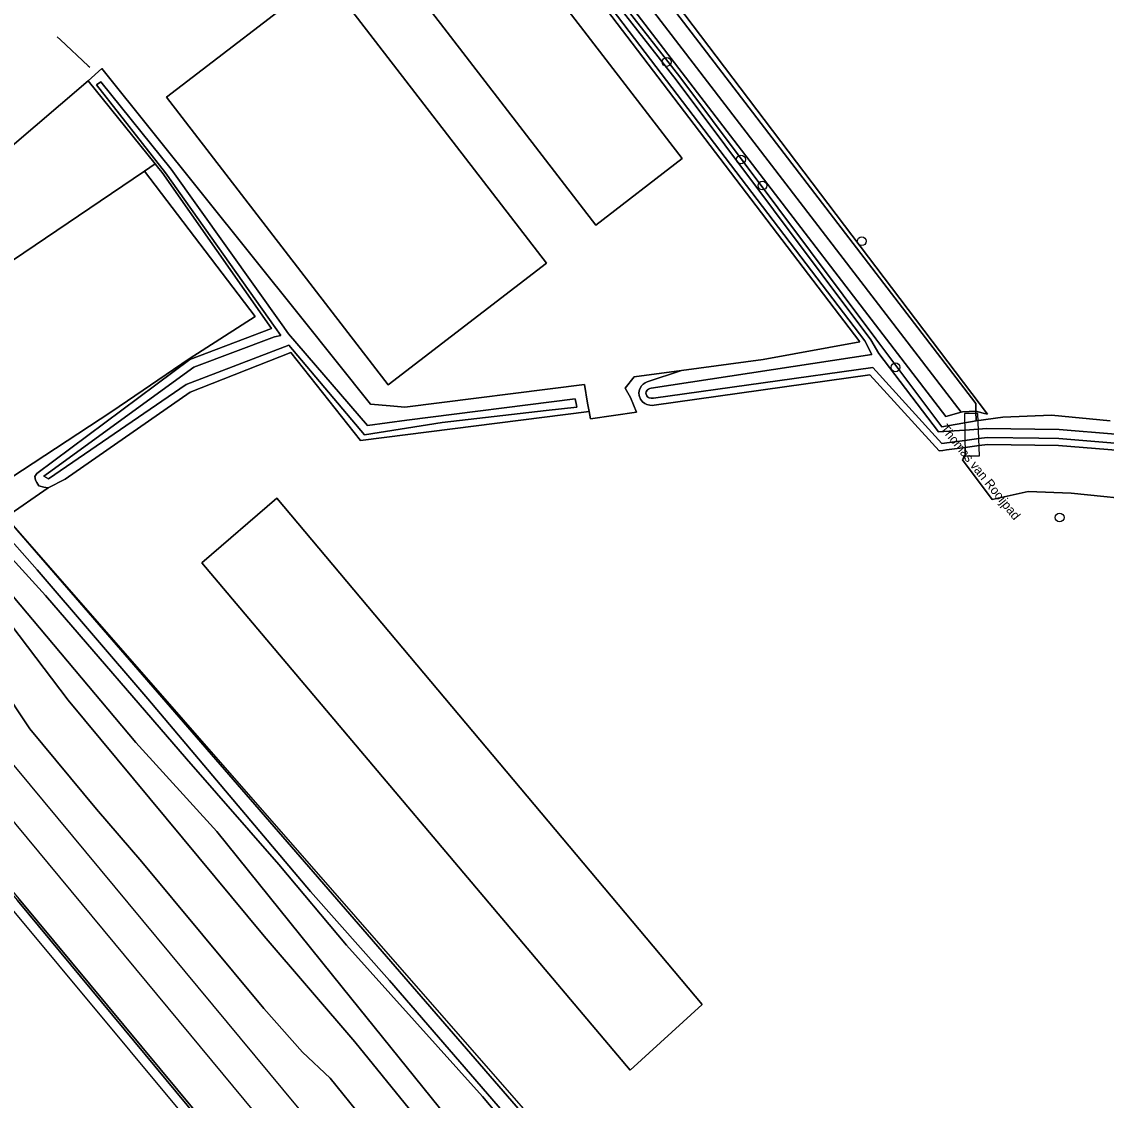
# Model space of a CAD drawing. Extents: x 164494 to 166241, y 382475 to 384495.
# Drawn here: x 165029.6 to 165148.9, y 382781.9 to 382900.5 of the extents above; entities that cross this region are included whole.
import ezdxf

# ---------------------------------------------------------------- set-up
doc = ezdxf.new("R2010")
doc.units = 0
for name, color, linetype in [('IMGEO_Boom', 7, 'Continuous'), ('IMGEO_Dek', 7, 'Continuous'), ('IMGEO_Duiker', 7, 'Continuous'), ('IMGEO_Erf', 7, 'Continuous'), ('IMGEO_Geluidsscherm', 7, 'Continuous'), ('IMGEO_Grasland_agrarisch', 7, 'Continuous'), ('IMGEO_Grasland_overig', 7, 'Continuous'), ('IMGEO_Groenvoorziening', 7, 'Continuous'), ('IMGEO_Hek', 7, 'Continuous'), ('IMGEO_Loofbos', 7, 'Continuous'), ('IMGEO_Muur', 7, 'Continuous'), ('IMGEO_Oever', 7, 'Continuous'), ('IMGEO_Open_loods', 7, 'Continuous'), ('IMGEO_Openbare_ruimte_label', 7, 'Continuous'), ('IMGEO_Pand', 7, 'Continuous'), ('IMGEO_Spoor', 7, 'Continuous'), ('IMGEO_Spoorbaan_halfverhard', 7, 'Continuous'), ('IMGEO_Terreindeel_zand', 7, 'Continuous'), ('IMGEO_Voetpad_open', 7, 'Continuous'), ('IMGEO_Waterloop', 7, 'Continuous')]:
    doc.layers.add(name, color=color, linetype=linetype)

msp = doc.modelspace()

# ---------------------------------------------------------------- linework, layer by layer
at = {"layer": 'IMGEO_Boom'}
for centre in [(165100.52, 382896.08), (165108.68, 382885.35), (165111.05, 382882.49), (165121.97, 382876.37), (165125.68, 382862.5), (165143.72, 382846)]:
    msp.add_circle(centre, 0.489, dxfattribs=at)
at = {"layer": 'IMGEO_Dek'}
msp.add_lwpolyline([(165134.72, 382857.43), (165133.26, 382857.44), (165133.35, 382852.77), (165134.9, 382852.79)], close=True, dxfattribs=at)
at = {"layer": 'IMGEO_Duiker'}
msp.add_lwpolyline([(165033.51, 382898.85), (165033.87, 382898.51), (165036.92, 382895.65), (165037.08, 382895.5)], dxfattribs=at)
at = {"layer": 'IMGEO_Erf'}
for points in [[(165066.6, 382948.67), (165135.81, 382857.34), (165135.31, 382857.48), (165134.52, 382857.7), (165134.55, 382856.63), (165137.47, 382857.02), (165142.85, 382857.23), (165149.29, 382856.63)], [(165007.04, 382918.4), (165019.13, 382899.87), (165028.02, 382886.4), (165036.89, 382893.98), (165038.4, 382895.36), (165060.39, 382867.92), (165067.96, 382858.46), (165070.13, 382858.26), (165071.71, 382858.12), (165091.47, 382860.62), (165091.82, 382858.55), (165091.98, 382857.66), (165092.13, 382856.83), (165097.2, 382857.59), (165096.55, 382859.18), (165095.94, 382860.23), (165096.95, 382861.46), (165102.13, 382862.15), (165111.11, 382863.35), (165121.76, 382865.31), (165087.09, 382910.83)]]:
    msp.add_lwpolyline(points, dxfattribs=at)
for points in [[(165068.39, 382909.77), (165077.89, 382917.07), (165102.23, 382885.46), (165092.72, 382878.14)], [(165062.93, 382905.58), (165087.31, 382873.97), (165069.89, 382860.57), (165045.51, 382892.2)]]:
    msp.add_lwpolyline(points, close=True, dxfattribs=at)
at = {"layer": 'IMGEO_Geluidsscherm'}
for points in [[(164967.63, 382879.18), (164968.42, 382878.23), (164969.05, 382877.2), (164972.8, 382871.38), (164985.66, 382855.99), (164987.91, 382853.25), (164988.14, 382852.97), (164988.99, 382851.92), (164989.37, 382851.47), (164991.3, 382849.12), (164999.17, 382839.73), (165029.12, 382803.9), (165050.12, 382778.61)], [(164967.82, 382879.34), (164968.62, 382878.38), (164969.26, 382877.33), (164973.01, 382871.52), (164985.85, 382856.15), (164988.33, 382853.13), (164989.19, 382852.08), (164991.49, 382849.28), (164999.36, 382839.9), (165029.31, 382804.06), (165050.54, 382778.5), (165051.4, 382777.46), (165054.48, 382773.76), (165066.57, 382759.13), (165083.41, 382739), (165089.76, 382731.36), (165108.9, 382708.37), (165112.45, 382704.1), (165112.77, 382703.72), (165113.64, 382702.68), (165126.37, 382687.38), (165133.17, 382679.13), (165141.63, 382668.9), (165151.85, 382656.58)]]:
    msp.add_lwpolyline(points, dxfattribs=at)
at = {"layer": 'IMGEO_Grasland_agrarisch'}
for points in [[(165007.04, 382918.4), (165006.82, 382918.81), (164995.87, 382903.23), (164991.28, 382896.51), (164988.37, 382892.57), (164988.58, 382892.31), (165012.89, 382863.66), (165043.1, 382884.07), (165044.28, 382884.87), (165036.89, 382893.98), (165028.02, 382886.4), (165019.13, 382899.87)], [(165057.65, 382848.13), (165104.41, 382792.47), (165096.49, 382785.26), (165049.42, 382841.01)]]:
    msp.add_lwpolyline(points, close=True, dxfattribs=at)
for points in [[(165153.59, 382847.8), (165144.99, 382848.66), (165140.26, 382848.85), (165136.29, 382847.99), (165133.03, 382852.34), (165133.35, 382852.77), (165133.33, 382853.7), (165131.27, 382853.43), (165130.88, 382853.38), (165130.48, 382853.33), (165122.87, 382861.67), (165099.15, 382858.33), (165098.93, 382858.32), (165098.68, 382858.33), (165098.32, 382858.42), (165098.11, 382858.53), (165097.87, 382858.72), (165097.64, 382859), (165097.53, 382859.29), (165097.49, 382859.4), (165097.46, 382859.71), (165097.52, 382860.07), (165097.74, 382860.47), (165097.93, 382860.66), (165098.17, 382860.81), (165098.39, 382860.91), (165102.13, 382862.15), (165096.95, 382861.46), (165095.94, 382860.23), (165096.55, 382859.18), (165097.2, 382857.59), (165092.13, 382856.83), (165091.98, 382857.66), (165066.86, 382854.46), (165059.2, 382864.13), (165048.13, 382859.76), (165034.39, 382850.21), (165032.5, 382849.27), (165027.86, 382846.04)], [(165028.15, 382845.7), (165139.3, 382717.42)]]:
    msp.add_lwpolyline(points, dxfattribs=at)
at = {"layer": 'IMGEO_Grasland_overig'}
for points in [[(165134.51, 382858.52), (165038.2, 382984.19), (165036.98, 382982.49), (165132.89, 382857.57), (165133.05, 382857.62), (165134.52, 382857.7)], [(165026.88, 382847.17), (165027.86, 382846.04), (165032.5, 382849.27), (165032.04, 382849.32), (165031.48, 382849.48), (165031.25, 382849.85), (165031.1, 382850.09), (165031.04, 382850.51), (165031.27, 382850.82), (165048.07, 382863.36), (165057.06, 382866.76), (165045.06, 382883.91), (165044.69, 382884.36), (165044.28, 382884.87), (165043.1, 382884.07), (165055.26, 382868.09), (165048.01, 382863.43), (165039.52, 382857.65), (165028.42, 382850.36), (165025.74, 382848.52)]]:
    msp.add_lwpolyline(points, close=True, dxfattribs=at)
for points in [[(165155.82, 382852.91), (165143.59, 382853.92), (165135.79, 382854.03), (165134.86, 382853.91), (165133.33, 382853.7), (165133.35, 382852.77), (165133.03, 382852.34), (165136.29, 382847.99), (165140.26, 382848.85), (165144.99, 382848.66), (165153.59, 382847.8)], [(165087.94, 382765.77), (165064.84, 382794.37), (165051.05, 382811.5), (165042.16, 382821.28), (165026.33, 382840.06)], [(165026.66, 382836.49), (165034.71, 382825.91), (165056.25, 382799.97), (165066.23, 382788.35), (165075.72, 382776.67)], [(165075.72, 382776.67), (165066.23, 382788.35), (165056.25, 382799.97), (165034.71, 382825.91), (165026.66, 382836.49)], [(165027.24, 382827.67), (165030.51, 382822.78), (165037.83, 382813.94), (165042.8, 382808.15), (165056.22, 382792.04), (165060.47, 382787.24), (165063.5, 382784.35), (165067.07, 382779.96)]]:
    msp.add_lwpolyline(points, dxfattribs=at)
at = {"layer": 'IMGEO_Groenvoorziening'}
for points in [[(165038.2, 382984.19), (165134.51, 382858.52), (165134.52, 382857.7), (165135.31, 382857.48), (165135.81, 382857.34), (165066.6, 382948.67), (165038.85, 382985.1)], [(165131.23, 382857.09), (165132.89, 382857.57), (165036.98, 382982.49), (165035.85, 382980.91), (165034.93, 382979.62), (165037.01, 382978.24), (165054.29, 382956.45), (165062.25, 382947.03)], [(165062.25, 382947.03), (165054.29, 382956.45), (165055.08, 382954.35), (165101.95, 382894.43), (165123.53, 382865.63), (165130.79, 382855.95), (165133.08, 382856.38), (165134.55, 382856.63), (165134.52, 382857.7), (165133.05, 382857.62), (165132.89, 382857.57), (165131.23, 382857.09)]]:
    msp.add_lwpolyline(points, close=True, dxfattribs=at)
for points in [[(165025.58, 382806.41), (165049.53, 382777.72)], [(165050.12, 382778.61), (165029.12, 382803.9)]]:
    msp.add_lwpolyline(points, dxfattribs=at)
at = {"layer": 'IMGEO_Hek'}
for points in [[(165038.85, 382985.1), (165066.6, 382948.67), (165135.81, 382857.34), (165135.31, 382857.48)], [(165132.89, 382857.57), (165131.23, 382857.09), (165062.25, 382947.03)], [(164973.54, 382889.66), (164975.81, 382891.38), (164981.3, 382895.69), (164983.94, 382897.77), (164985.02, 382896.52), (164988.37, 382892.57), (164988.58, 382892.31), (165012.89, 382863.66), (165025.74, 382848.52), (165028.15, 382845.7), (165085.5, 382780.16), (165088.54, 382776.69), (165137.4, 382721.35), (165139.82, 382718.71), (165140.36, 382718.08), (165158.11, 382697.26)], [(165133.05, 382857.62), (165132.89, 382857.57)], [(165135.31, 382857.48), (165134.52, 382857.7)], [(165096.49, 382785.26), (165049.42, 382841.01), (165057.65, 382848.13), (165104.41, 382792.47), (165096.49, 382785.26)]]:
    msp.add_lwpolyline(points, dxfattribs=at)
at = {"layer": 'IMGEO_Loofbos'}
msp.add_lwpolyline([(165104.41, 382792.47), (165057.65, 382848.13), (165049.42, 382841.01), (165096.49, 382785.26)], close=True, dxfattribs=at)
at = {"layer": 'IMGEO_Muur'}
for points in [[(165029.12, 382803.9), (165050.12, 382778.61)], [(165050.54, 382778.5), (165029.31, 382804.06)]]:
    msp.add_lwpolyline(points, dxfattribs=at)
at = {"layer": 'IMGEO_Oever'}
for points in [[(165054.63, 382954.09), (165101.55, 382894.12), (165122.97, 382865.53), (165123.85, 382864.03), (165130.41, 382855.41), (165133.29, 382855.61), (165134.79, 382855.72), (165135.68, 382855.78), (165143.67, 382855.67), (165156.07, 382854.65)], [(165149.29, 382856.63), (165142.85, 382857.23), (165137.47, 382857.02), (165134.55, 382856.63), (165133.08, 382856.38), (165130.79, 382855.95), (165123.53, 382865.63), (165101.95, 382894.43), (165055.08, 382954.35)], [(165155.93, 382853.67), (165143.62, 382854.69), (165141.45, 382854.72), (165135.74, 382854.8), (165134.83, 382854.68), (165133.31, 382854.48), (165130.78, 382854.15), (165127.15, 382858.12), (165123.17, 382862.49), (165099.08, 382859.1), (165098.94, 382859.1), (165098.8, 382859.1), (165098.6, 382859.15), (165098.53, 382859.19), (165098.41, 382859.28), (165098.32, 382859.38), (165098.25, 382859.57), (165098.24, 382859.67), (165098.27, 382859.81), (165098.37, 382860), (165098.42, 382860.05), (165098.53, 382860.12), (165098.67, 382860.18), (165098.81, 382860.23), (165123.08, 382863.91), (165122.32, 382865.41), (165087.5, 382911.14)], [(165087.09, 382910.83), (165121.76, 382865.31), (165111.11, 382863.35), (165102.13, 382862.15), (165098.39, 382860.91), (165098.17, 382860.81), (165097.93, 382860.66), (165097.74, 382860.47), (165097.52, 382860.07), (165097.46, 382859.71), (165097.49, 382859.4), (165097.53, 382859.29), (165097.64, 382859), (165097.87, 382858.72), (165098.11, 382858.53), (165098.32, 382858.42), (165098.68, 382858.33), (165098.93, 382858.32), (165099.15, 382858.33), (165122.87, 382861.67), (165130.48, 382853.33), (165130.88, 382853.38), (165131.27, 382853.43), (165133.33, 382853.7), (165134.86, 382853.91), (165135.79, 382854.03), (165143.59, 382853.92), (165155.82, 382852.91)]]:
    msp.add_lwpolyline(points, dxfattribs=at)
for points in [[(165091.98, 382857.66), (165091.82, 382858.55), (165091.47, 382860.62), (165071.71, 382858.12), (165070.13, 382858.26), (165067.96, 382858.46), (165060.39, 382867.92), (165038.4, 382895.36), (165036.89, 382893.98), (165044.28, 382884.87), (165044.69, 382884.36), (165045.06, 382883.91), (165057.06, 382866.76), (165048.07, 382863.36), (165031.27, 382850.82), (165031.04, 382850.51), (165031.1, 382850.09), (165031.25, 382849.85), (165031.48, 382849.48), (165032.04, 382849.32), (165032.5, 382849.27), (165034.39, 382850.21), (165048.13, 382859.76), (165059.2, 382864.13), (165066.86, 382854.46)], [(165038.29, 382893.89), (165046.03, 382884.28), (165058.24, 382867.17), (165058.94, 382866.19), (165067.62, 382856.11), (165071.96, 382856.69), (165090.45, 382859.05), (165090.61, 382858.34), (165090.65, 382858.14), (165087.27, 382857.75), (165075.85, 382856.45), (165067.28, 382855.1), (165058.97, 382864.96), (165047.68, 382860.61), (165032.53, 382850.25), (165032.02, 382850.56), (165032.53, 382850.91), (165048.53, 382862.52), (165057.39, 382865.86), (165058.11, 382866.02), (165057.48, 382866.9), (165045.41, 382883.88), (165037.84, 382893.56)], [(165028.15, 382845.7), (165027.12, 382844.95), (165031.29, 382840.23), (165043.46, 382826.05), (165061.34, 382804.88), (165070.04, 382795.12), (165083.17, 382779.94), (165086.92, 382776.02), (165096.77, 382765.03), (165105.02, 382754.95), (165119.18, 382738.24), (165138.17, 382716.84), (165138.56, 382717.02), (165173.63, 382676.45), (165158.11, 382697.26), (165139.3, 382717.42)], [(165026.07, 382844.19), (165024.02, 382842.71), (165026.33, 382840.06), (165042.16, 382821.28), (165051.05, 382811.5), (165064.84, 382794.37), (165087.94, 382765.77), (165094.27, 382759.82), (165097.07, 382758.22), (165099.41, 382756.22), (165102.09, 382753.62), (165109.2, 382746.55), (165114.26, 382740.8), (165135.14, 382715.41), (165137.45, 382716.5), (165119.24, 382737.14), (165101.16, 382758.17), (165087.4, 382773.84), (165080.27, 382782.34), (165065.31, 382798.98), (165057.87, 382807.85), (165047.71, 382819.46), (165032.21, 382837.42), (165027.04, 382843.06)]]:
    msp.add_lwpolyline(points, close=True, dxfattribs=at)
at = {"layer": 'IMGEO_Open_loods'}
msp.add_lwpolyline([(165077.89, 382917.07), (165068.39, 382909.77), (165092.72, 382878.14), (165102.23, 382885.46)], close=True, dxfattribs=at)
at = {"layer": 'IMGEO_Pand'}
msp.add_lwpolyline([(165062.93, 382905.58), (165045.51, 382892.2), (165069.89, 382860.57), (165087.31, 382873.97)], close=True, dxfattribs=at)
at = {"layer": 'IMGEO_Spoor'}
for points in [[(164971.84, 382886.62), (165028.93, 382818.52), (165059.9, 382781.2), (165071.68, 382767.17), (165111.26, 382719.76), (165163.2, 382658.4), (165174.6, 382645.25), (165185.3, 382632.69), (165237.74, 382570.35), (165244.67, 382561.92)], [(164968.87, 382884.12), (165014.68, 382829.39), (165077.86, 382753.28), (165088.51, 382740.65), (165118.9, 382704.2), (165145.22, 382672.37), (165159.72, 382654.6), (165190.85, 382616.84), (165202.75, 382602.69), (165235.6, 382563.21)]]:
    msp.add_lwpolyline(points, dxfattribs=at)
at = {"layer": 'IMGEO_Spoorbaan_halfverhard'}
for points in [[(165067.07, 382779.96), (165063.5, 382784.35), (165060.47, 382787.24), (165056.22, 382792.04), (165042.8, 382808.15), (165037.83, 382813.94), (165030.51, 382822.78), (165027.24, 382827.67)], [(165029.31, 382804.06), (165050.54, 382778.5)]]:
    msp.add_lwpolyline(points, dxfattribs=at)
at = {"layer": 'IMGEO_Terreindeel_zand'}
msp.add_lwpolyline([(165013.09, 382863.43), (165025.74, 382848.52), (165028.42, 382850.36), (165039.52, 382857.65), (165048.01, 382863.43), (165055.26, 382868.09), (165043.1, 382884.07), (165012.89, 382863.66)], close=True, dxfattribs=at)
at = {"layer": 'IMGEO_Voetpad_open'}
msp.add_lwpolyline([(165134.72, 382857.43), (165133.26, 382857.44), (165133.35, 382852.77), (165134.9, 382852.79)], close=True, dxfattribs=at)
at = {"layer": 'IMGEO_Waterloop'}
for points in [[(165156.07, 382854.65), (165143.67, 382855.67), (165135.68, 382855.78), (165134.79, 382855.72), (165133.29, 382855.61), (165130.41, 382855.41), (165123.85, 382864.03), (165122.97, 382865.53), (165101.55, 382894.12), (165054.63, 382954.09)], [(165087.5, 382911.14), (165122.32, 382865.41), (165123.08, 382863.91), (165098.81, 382860.23), (165098.67, 382860.18), (165098.53, 382860.12), (165098.42, 382860.05), (165098.37, 382860), (165098.27, 382859.81), (165098.24, 382859.67), (165098.25, 382859.57), (165098.32, 382859.38), (165098.41, 382859.28), (165098.53, 382859.19), (165098.6, 382859.15), (165098.8, 382859.1), (165098.94, 382859.1), (165099.08, 382859.1), (165123.17, 382862.49), (165127.15, 382858.12), (165130.78, 382854.15), (165133.31, 382854.48), (165134.83, 382854.68), (165135.74, 382854.8), (165141.45, 382854.72), (165143.62, 382854.69), (165155.93, 382853.67)]]:
    msp.add_lwpolyline(points, dxfattribs=at)
for points in [[(165058.94, 382866.19), (165058.24, 382867.17), (165046.03, 382884.28), (165038.29, 382893.89), (165037.84, 382893.56), (165045.41, 382883.88), (165057.48, 382866.9), (165058.11, 382866.02), (165057.39, 382865.86), (165048.53, 382862.52), (165032.53, 382850.91), (165032.02, 382850.56), (165032.53, 382850.25), (165047.68, 382860.61), (165058.97, 382864.96), (165067.28, 382855.1), (165075.85, 382856.45), (165087.27, 382857.75), (165090.65, 382858.14), (165090.61, 382858.34), (165090.45, 382859.05), (165071.96, 382856.69), (165067.62, 382856.11)], [(165027.12, 382844.95), (165026.07, 382844.19), (165027.04, 382843.06), (165032.21, 382837.42), (165047.71, 382819.46), (165057.87, 382807.85), (165065.31, 382798.98), (165080.27, 382782.34), (165087.4, 382773.84), (165101.16, 382758.17), (165119.24, 382737.14), (165137.45, 382716.5), (165138.17, 382716.84), (165119.18, 382738.24), (165105.02, 382754.95), (165096.77, 382765.03), (165086.92, 382776.02), (165083.17, 382779.94), (165070.04, 382795.12), (165061.34, 382804.88), (165043.46, 382826.05), (165031.29, 382840.23)]]:
    msp.add_lwpolyline(points, close=True, dxfattribs=at)

# ---------------------------------------------------------------- texts
at = {"layer": 'IMGEO_Openbare_ruimte_label'}
msp.add_text('Thomas van Rooijpad', height=1, rotation=308.8744, dxfattribs=at).set_placement((165130.56, 382855.75))

doc.saveas('drawing.dxf')
